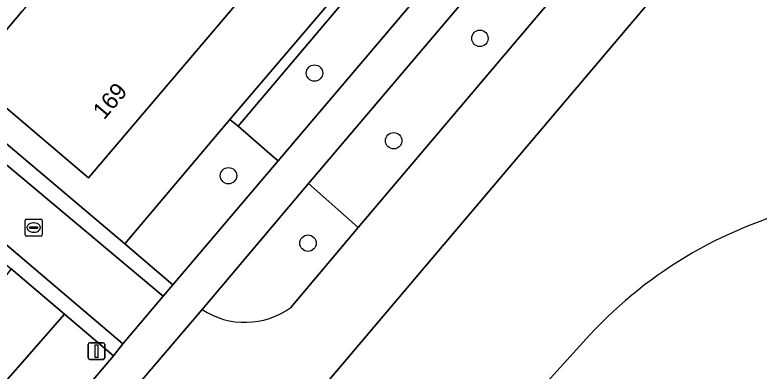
# Model space of a CAD drawing. Extents: x 156412 to 157779, y 382335 to 383768.
# Drawn here: x 157035.16 to 157079.52, y 382589.54 to 382610.78 of the extents above; entities that cross this region are included whole.
import ezdxf

# ---------------------------------------------------------------- set-up
doc = ezdxf.new("R2010")
doc.units = 0
for name, color, linetype in [('IMGEO_Berm_groen', 7, 'Continuous'), ('IMGEO_Boom', 7, 'Continuous'), ('IMGEO_Erf', 7, 'Continuous'), ('IMGEO_Groenvoorziening', 7, 'Continuous'), ('IMGEO_Haag', 7, 'Continuous'), ('IMGEO_Kolk', 7, 'Continuous'), ('IMGEO_Lichtmast', 7, 'Continuous'), ('IMGEO_Pand', 7, 'Continuous'), ('IMGEO_Pand_nummerreeks', 7, 'Continuous'), ('IMGEO_Rijbaan_lokaal_open', 7, 'Continuous'), ('IMGEO_Voetpad_open', 7, 'Continuous')]:
    doc.layers.add(name, color=color, linetype=linetype)

msp = doc.modelspace()

# ---------------------------------------------------------------- linework, layer by layer
at = {"layer": 'IMGEO_Berm_groen'}
msp.add_lwpolyline([(157071.28, 382622.71), (157065.426, 382615.796), (157052.666, 382600.724), (157055.623, 382598.094), (157068.427, 382613.254)], dxfattribs=at)
at = {"layer": 'IMGEO_Boom'}
for centre in [(157062.877, 382609.38), (157053.018, 382607.312), (157057.737, 382603.275), (157047.889, 382601.19), (157052.628, 382597.168)]:
    msp.add_circle(centre, 0.489, dxfattribs=at)
at = {"layer": 'IMGEO_Erf'}
for points in [[(157032.018, 382606.037), (157033.314, 382604.947), (157032.946, 382604.52), (157041.703, 382597.123), (157047.972, 382604.539), (157048.196, 382604.798), (157060.586, 382619.348), (157029.826, 382645.416), (156987.205, 382681.476), (156986.214, 382682.315), (156984.143, 382684.067), (156942.915, 382635.543), (156901.626, 382586.899), (156977.949, 382522.266), (156980.608, 382525.348), (156995.995, 382543.705), (156987.057, 382551.292)], [(157052.541, 382616.375), (157039.552, 382601.073), (157032.351, 382607.17), (157035.583, 382610.995)], [(157031.936, 382585.906), (157038.117, 382592.933), (157034.938, 382595.632), (157034.651, 382595.29), (157027.77, 382601.127)]]:
    msp.add_lwpolyline(points, dxfattribs=at)
at = {"layer": 'IMGEO_Groenvoorziening'}
for points in [[(156987.719, 382682.101), (156987.43, 382681.751), (156987.205, 382681.476), (157029.826, 382645.416), (157060.586, 382619.348), (157048.196, 382604.798), (157047.972, 382604.539), (157048.46, 382604.143), (157061.516, 382619.589)], [(157050.846, 382602.075), (157050.632, 382602.262), (157048.46, 382604.143), (157047.972, 382604.539), (157041.703, 382597.123), (157044.581, 382594.691)], [(157041.035, 382590.456), (157038.117, 382592.933), (157031.936, 382585.906), (157032.49, 382585.447), (157034.725, 382583.574), (157034.993, 382583.337)]]:
    msp.add_lwpolyline(points, close=True, dxfattribs=at)
for points in [[(157061.516, 382619.589), (157048.46, 382604.143), (157050.632, 382602.262), (157050.846, 382602.075), (157063.375, 382616.844)], [(157075.166, 382614.156), (157051.486, 382586.188), (157058.945, 382580.128), (157069.412, 382591.686)], [(157055.623, 382598.094), (157052.666, 382600.724), (157046.313, 382593.22)], [(157051.6, 382593.33), (157055.623, 382598.094)], [(157069.412, 382591.686), (157058.945, 382580.128), (157059.021, 382580.066)]]:
    msp.add_lwpolyline(points, dxfattribs=at)
for centre, radius, start, end in [((157088.667, 382573.848), 26.248, 102.7578, 137.1876), ((157088.667, 382573.848), 26.248, 102.7578, 137.1876), ((157048.877, 382597.102), 4.653, 236.5594, 305.8244)]:
    msp.add_arc(centre, radius, start, end, dxfattribs=at)
at = {"layer": 'IMGEO_Haag'}
for points in [[(156987.719, 382682.101), (156987.43, 382681.751), (156987.205, 382681.476), (157029.826, 382645.416), (157060.586, 382619.348), (157048.196, 382604.798), (157047.972, 382604.539), (157048.46, 382604.143), (157061.516, 382619.589)], [(157050.846, 382602.075), (157050.632, 382602.262), (157048.46, 382604.143), (157047.972, 382604.539), (157041.703, 382597.123), (157044.581, 382594.691)], [(157041.035, 382590.456), (157038.117, 382592.933), (157031.936, 382585.906), (157032.49, 382585.447), (157034.725, 382583.574), (157034.993, 382583.337)]]:
    msp.add_lwpolyline(points, close=True, dxfattribs=at)
for points in [[(157055.623, 382598.094), (157052.666, 382600.724), (157046.313, 382593.22)], [(157051.6, 382593.33), (157055.623, 382598.094)]]:
    msp.add_lwpolyline(points, dxfattribs=at)
msp.add_arc((157048.877, 382597.102), 4.653, 236.5594, 305.8244, dxfattribs=at)
at = {"layer": 'IMGEO_Kolk'}
for p, q in [((157035.852, 382598.596), (157036.704, 382598.596)), ((157035.777, 382597.67), (157035.777, 382598.522)), ((157036.079, 382598.139), (157036.477, 382598.139)), ((157036.265, 382598.376), (157036.29, 382598.376)), ((157036.778, 382598.522), (157036.778, 382597.67)), ((157036.036, 382598.09), (157036.036, 382598.102)), ((157036.474, 382598.053), (157036.076, 382598.053)), ((157036.288, 382597.816), (157036.263, 382597.816)), ((157036.52, 382598.102), (157036.52, 382598.09)), ((157036.704, 382597.596), (157035.852, 382597.596))]:
    msp.add_line(p, q, dxfattribs=at)
for points in [[(157035.852, 382598.596), (157036.704, 382598.596)], [(157035.777, 382597.67), (157035.777, 382598.522)], [(157036.778, 382598.522), (157036.778, 382597.67)], [(157036.704, 382597.596), (157035.852, 382597.596)]]:
    msp.add_lwpolyline(points, dxfattribs=at)
for centre, radius, start, end in [((157035.854, 382598.52), 0.0765, 91.552, 178.448), ((157035.854, 382598.52), 0.0765, 91.552, 178.448), ((157036.702, 382598.52), 0.0765, 1.552, 88.448), ((157036.702, 382598.52), 0.0765, 1.552, 88.448), ((157036.076, 382598.099), 0.0403, 85.8775, 175.7526), ((157036.481, 382598.101), 0.0386, 1.7309, 96.639), ((157036.073, 382598.089), 0.0366, 178.938, 274.7102), ((157036.477, 382598.096), 0.043, 264.8664, 352.4533), ((157035.854, 382597.672), 0.0765, 181.552, 268.448), ((157035.854, 382597.672), 0.0765, 181.552, 268.448), ((157036.702, 382597.672), 0.0765, 271.552, 358.448), ((157036.702, 382597.672), 0.0765, 271.552, 358.448)]:
    msp.add_arc(centre, radius, start, end, dxfattribs=at)
for centre, major_axis, ratio, start_param, end_param in [((157036.264, 382598.096), (-0.387, 0.002), 0.722429, 4.712389, 7.853982), ((157036.289, 382598.096), (-0.39, 0.002), 0.717154, 1.570796, 4.712389)]:
    msp.add_ellipse(centre, major_axis=major_axis, ratio=ratio, start_param=start_param, end_param=end_param, dxfattribs=at)
at = {"layer": 'IMGEO_Lichtmast'}
for p, q in [((157039.522, 382590.334), (157039.522, 382591.134)), ((157039.522, 382591.134), (157039.522, 382590.334)), ((157039.622, 382591.234), (157040.412, 382591.234)), ((157040.412, 382591.234), (157039.622, 382591.234)), ((157040.512, 382591.134), (157040.512, 382590.334)), ((157040.512, 382590.334), (157040.512, 382591.134)), ((157040.412, 382590.234), (157039.622, 382590.234)), ((157039.622, 382590.234), (157040.412, 382590.234))]:
    msp.add_line(p, q, dxfattribs=at)
msp.add_lwpolyline([(157039.942, 382591.109), (157040.092, 382591.109), (157040.092, 382590.359), (157039.942, 382590.359), (157039.942, 382591.109)], dxfattribs=at)
for centre, start, end in [((157039.622, 382591.134), 90, 180), ((157039.622, 382591.134), 90, 180), ((157040.412, 382591.134), 0, 90), ((157040.412, 382591.134), 360, 90), ((157039.622, 382590.334), 180, 270), ((157039.622, 382590.334), 180, 270), ((157040.412, 382590.334), 270, 0), ((157040.412, 382590.334), 270, 0)]:
    msp.add_arc(centre, 0.1, start, end, dxfattribs=at)
at = {"layer": 'IMGEO_Pand'}
msp.add_lwpolyline([(157046.553, 382623.934), (157035.583, 382610.995), (157032.351, 382607.17), (157039.552, 382601.073), (157052.541, 382616.375), (157054.766, 382618.997), (157050.957, 382622.22), (157047.699, 382624.977), (157047.549, 382625.107)], close=True, dxfattribs=at)
at = {"layer": 'IMGEO_Rijbaan_lokaal_open'}
for points in [[(157070.73, 382615.98), (157068.427, 382613.254), (157055.623, 382598.094), (157051.6, 382593.33)], [(157026.802, 382557.033), (157050.943, 382585.546), (157051.486, 382586.188), (157075.166, 382614.156)], [(157028.653, 382602.153), (157041.599, 382591.168), (157043.996, 382594.008), (157030.951, 382604.943)], [(157046.313, 382593.22), (157042.73, 382588.992)]]:
    msp.add_lwpolyline(points, dxfattribs=at)
msp.add_arc((157048.877, 382597.102), 4.653, 236.5594, 305.8244, dxfattribs=at)
at = {"layer": 'IMGEO_Voetpad_open'}
for points in [[(157069.998, 382624.651), (157063.715, 382617.245), (157063.375, 382616.844), (157050.846, 382602.075), (157044.581, 382594.691), (157043.996, 382594.008), (157041.599, 382591.168), (157041.035, 382590.456), (157034.993, 382583.337), (157023.048, 382569.261), (157022.187, 382568.261)], [(157020.132, 382562.262), (157024.76, 382567.784), (157036.559, 382581.709), (157042.73, 382588.992), (157046.313, 382593.22), (157052.666, 382600.724), (157065.426, 382615.796), (157071.28, 382622.71)], [(157030.951, 382604.943), (157043.996, 382594.008), (157044.581, 382594.691), (157041.703, 382597.123), (157032.946, 382604.52), (157031.577, 382605.677)], [(157028.061, 382601.47), (157034.938, 382595.632), (157038.117, 382592.933), (157041.035, 382590.456), (157041.599, 382591.168), (157028.653, 382602.153)]]:
    msp.add_lwpolyline(points, dxfattribs=at)

# ---------------------------------------------------------------- texts
at = {"layer": 'IMGEO_Pand_nummerreeks'}
msp.add_text('169', height=1, rotation=49.6754, dxfattribs=at).set_placement((157040.478, 382604.483))

doc.saveas('drawing.dxf')
